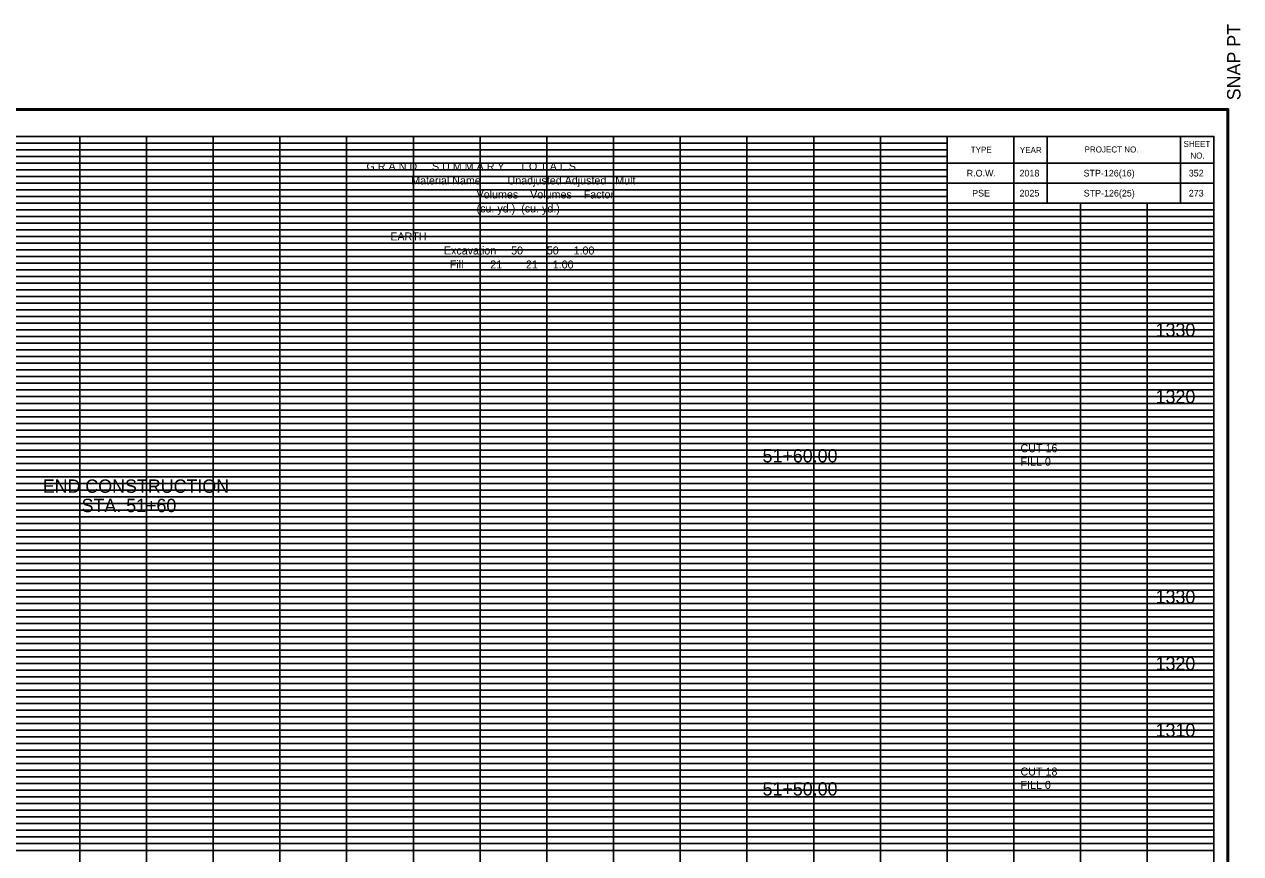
# Model space of a CAD drawing. Extents: x 980 to 1324, y 978 to 1227.
# Drawn here: x 1141.7 to 1324, y 1102.5 to 1226.8 of the extents above; entities that cross this region are included whole.
import ezdxf

# ---------------------------------------------------------------- set-up
doc = ezdxf.new("R2010")
doc.units = 0
for name, color, linetype in [('DESIGN - SCRATCH - User 1', 7, 'Continuous'), ('DESIGN - SHEET - Corner Text', 7, 'Continuous'), ('DESIGN - SHEET - Light Grid', 7, 'Continuous'), ('DESIGN - SHEET - Linework', 7, 'Continuous'), ('DESIGN - SHEET - Plot Shape', 7, 'Continuous'), ('DESIGN - TYPICAL - Finished Grade and Subgrade', 7, 'Continuous'), ('DESIGN - TYPICAL - Text', 7, 'Continuous')]:
    doc.layers.add(name, color=color, linetype=linetype)

# ---------------------------------------------------------------- blocks, each defined once
blk = doc.blocks.new('XSTSHT')
at = {"layer": 'DESIGN - SCRATCH - User 1'}
for p, q in [((28.5, 20.45), (28.5, 20.45)), ((29.24, 20.45), (29.24, 20.45)), ((30.49, 20.45), (30.49, 20.45)), ((31.74, 20.45), (31.74, 20.45)), ((28.5, 20.15), (28.5, 20.15)), ((29.24, 20.15), (29.24, 20.15)), ((30.49, 20.15), (30.49, 20.15)), ((31.74, 20.15), (31.74, 20.15))]:
    blk.add_line(p, q, dxfattribs=at)
at = {"layer": 'DESIGN - SHEET - Light Grid'}
for p, q in [((8, 20.9), (16, 20.9)), ((8, 20.8), (16, 20.8)), ((16, 20.9), (24, 20.9)), ((16, 20.8), (24, 20.8)), ((24, 20.9), (28, 20.9)), ((24, 20.8), (28, 20.8)), ((8, 20.7), (16, 20.7)), ((16, 20.7), (24, 20.7)), ((24, 20.7), (28, 20.7)), ((8, 20.6), (16, 20.6)), ((8, 20.5), (16, 20.5)), ((16, 20.6), (24, 20.6)), ((16, 20.5), (24, 20.5)), ((24, 20.6), (28, 20.6)), ((24, 20.5), (28, 20.5)), ((8, 20.4), (16, 20.4)), ((8, 20.3), (16, 20.3)), ((16, 20.4), (24, 20.4)), ((16, 20.3), (24, 20.3)), ((24, 20.4), (28, 20.4)), ((24, 20.3), (28, 20.3)), ((8, 20.2), (16, 20.2)), ((8, 20.1), (16, 20.1)), ((16, 20.2), (24, 20.2)), ((16, 20.1), (24, 20.1)), ((24, 20.2), (28, 20.2)), ((24, 20.1), (28, 20.1)), ((8, 19.9), (16, 19.9)), ((16, 19.9), (24, 19.9)), ((24, 19.9), (32, 19.9)), ((8, 19.8), (16, 19.8)), ((8, 19.7), (16, 19.7)), ((16, 19.8), (24, 19.8)), ((16, 19.7), (24, 19.7)), ((24, 19.8), (32, 19.8)), ((24, 19.7), (32, 19.7)), ((8, 19.6), (16, 19.6)), ((16, 19.6), (24, 19.6)), ((24, 19.6), (32, 19.6)), ((8, 19.5), (16, 19.5)), ((8, 19.4), (16, 19.4)), ((16, 19.5), (24, 19.5)), ((16, 19.4), (24, 19.4)), ((24, 19.5), (32, 19.5)), ((24, 19.4), (32, 19.4)), ((8, 19.3), (16, 19.3)), ((8, 19.2), (16, 19.2)), ((16, 19.3), (24, 19.3)), ((16, 19.2), (24, 19.2)), ((24, 19.3), (32, 19.3)), ((24, 19.2), (32, 19.2)), ((8, 19.1), (16, 19.1)), ((16, 19.1), (24, 19.1)), ((24, 19.1), (32, 19.1)), ((8, 18.9), (16, 18.9)), ((8, 18.8), (16, 18.8)), ((16, 18.9), (24, 18.9)), ((16, 18.8), (24, 18.8)), ((24, 18.9), (32, 18.9)), ((24, 18.8), (32, 18.8)), ((8, 18.7), (16, 18.7)), ((8, 18.6), (16, 18.6)), ((16, 18.7), (24, 18.7)), ((16, 18.6), (24, 18.6)), ((24, 18.7), (32, 18.7)), ((24, 18.6), (32, 18.6)), ((8, 18.5), (16, 18.5)), ((16, 18.5), (24, 18.5)), ((24, 18.5), (32, 18.5)), ((8, 18.4), (16, 18.4)), ((8, 18.3), (16, 18.3)), ((16, 18.4), (24, 18.4)), ((16, 18.3), (24, 18.3)), ((24, 18.4), (32, 18.4)), ((24, 18.3), (32, 18.3)), ((8, 18.2), (16, 18.2)), ((8, 18.1), (16, 18.1)), ((16, 18.2), (24, 18.2)), ((16, 18.1), (24, 18.1)), ((24, 18.2), (32, 18.2)), ((24, 18.1), (32, 18.1)), ((8, 17.9), (16, 17.9)), ((16, 17.9), (24, 17.9)), ((24, 17.9), (32, 17.9)), ((8, 17.8), (16, 17.8)), ((8, 17.7), (16, 17.7)), ((16, 17.8), (24, 17.8)), ((16, 17.7), (24, 17.7)), ((24, 17.8), (32, 17.8)), ((24, 17.7), (32, 17.7)), ((8, 17.6), (16, 17.6)), ((16, 17.6), (24, 17.6)), ((24, 17.6), (32, 17.6)), ((8, 17.5), (16, 17.5)), ((8, 17.4), (16, 17.4)), ((16, 17.5), (24, 17.5)), ((16, 17.4), (24, 17.4)), ((24, 17.5), (32, 17.5)), ((24, 17.4), (32, 17.4)), ((8, 17.3), (16, 17.3)), ((8, 17.2), (16, 17.2)), ((16, 17.3), (24, 17.3)), ((16, 17.2), (24, 17.2)), ((24, 17.3), (32, 17.3)), ((24, 17.2), (32, 17.2)), ((8, 17.1), (16, 17.1)), ((16, 17.1), (24, 17.1)), ((24, 17.1), (32, 17.1)), ((8, 16.9), (16, 16.9)), ((8, 16.8), (16, 16.8)), ((16, 16.9), (24, 16.9)), ((16, 16.8), (24, 16.8)), ((24, 16.9), (32, 16.9)), ((24, 16.8), (32, 16.8)), ((8, 16.7), (16, 16.7)), ((8, 16.6), (16, 16.6)), ((16, 16.7), (24, 16.7)), ((16, 16.6), (24, 16.6)), ((24, 16.7), (32, 16.7)), ((24, 16.6), (32, 16.6)), ((8, 16.5), (16, 16.5)), ((16, 16.5), (24, 16.5)), ((24, 16.5), (32, 16.5)), ((8, 16.4), (16, 16.4)), ((8, 16.3), (16, 16.3)), ((16, 16.4), (24, 16.4)), ((16, 16.3), (24, 16.3)), ((24, 16.4), (32, 16.4)), ((24, 16.3), (32, 16.3)), ((8, 16.2), (16, 16.2)), ((8, 16.1), (16, 16.1)), ((16, 16.2), (24, 16.2)), ((16, 16.1), (24, 16.1)), ((24, 16.2), (32, 16.2)), ((24, 16.1), (32, 16.1)), ((8, 15.9), (16, 15.9)), ((16, 15.9), (24, 15.9)), ((24, 15.9), (32, 15.9)), ((8, 15.8), (16, 15.8)), ((8, 15.7), (16, 15.7)), ((16, 15.8), (24, 15.8)), ((16, 15.7), (24, 15.7)), ((24, 15.8), (32, 15.8)), ((24, 15.7), (32, 15.7)), ((8, 15.6), (16, 15.6)), ((8, 15.5), (16, 15.5)), ((16, 15.6), (24, 15.6)), ((16, 15.5), (24, 15.5)), ((24, 15.6), (32, 15.6)), ((24, 15.5), (32, 15.5)), ((8, 15.4), (16, 15.4)), ((16, 15.4), (24, 15.4)), ((24, 15.4), (32, 15.4)), ((8, 15.3), (16, 15.3)), ((8, 15.2), (16, 15.2)), ((16, 15.3), (24, 15.3)), ((16, 15.2), (24, 15.2)), ((24, 15.3), (32, 15.3)), ((24, 15.2), (32, 15.2)), ((8, 15.1), (16, 15.1)), ((16, 15.1), (24, 15.1)), ((24, 15.1), (32, 15.1)), ((8, 14.9), (16, 14.9)), ((8, 14.8), (16, 14.8)), ((16, 14.9), (24, 14.9)), ((16, 14.8), (24, 14.8)), ((24, 14.9), (32, 14.9)), ((24, 14.8), (32, 14.8)), ((8, 14.7), (16, 14.7)), ((8, 14.6), (16, 14.6)), ((16, 14.7), (24, 14.7)), ((16, 14.6), (24, 14.6)), ((24, 14.7), (32, 14.7)), ((24, 14.6), (32, 14.6)), ((8, 14.5), (16, 14.5)), ((16, 14.5), (24, 14.5)), ((24, 14.5), (32, 14.5)), ((8, 14.4), (16, 14.4)), ((8, 14.3), (16, 14.3)), ((16, 14.4), (24, 14.4)), ((16, 14.3), (24, 14.3)), ((24, 14.4), (32, 14.4)), ((24, 14.3), (32, 14.3)), ((8, 14.2), (16, 14.2)), ((8, 14.1), (16, 14.1)), ((16, 14.2), (24, 14.2)), ((16, 14.1), (24, 14.1)), ((24, 14.2), (32, 14.2)), ((24, 14.1), (32, 14.1)), ((8, 13.9), (16, 13.9)), ((16, 13.9), (24, 13.9)), ((24, 13.9), (32, 13.9)), ((8, 13.8), (16, 13.8)), ((8, 13.7), (16, 13.7)), ((16, 13.8), (24, 13.8)), ((16, 13.7), (24, 13.7)), ((24, 13.8), (32, 13.8)), ((24, 13.7), (32, 13.7)), ((8, 13.6), (16, 13.6)), ((8, 13.5), (16, 13.5)), ((16, 13.6), (24, 13.6)), ((16, 13.5), (24, 13.5)), ((24, 13.6), (32, 13.6)), ((24, 13.5), (32, 13.5)), ((8, 13.4), (16, 13.4)), ((16, 13.4), (24, 13.4)), ((24, 13.4), (32, 13.4)), ((8, 13.3), (16, 13.3)), ((8, 13.2), (16, 13.2)), ((16, 13.3), (24, 13.3)), ((16, 13.2), (24, 13.2)), ((24, 13.3), (32, 13.3)), ((24, 13.2), (32, 13.2)), ((8, 13.1), (16, 13.1)), ((16, 13.1), (24, 13.1)), ((24, 13.1), (32, 13.1)), ((8, 12.9), (16, 12.9)), ((8, 12.8), (16, 12.8)), ((16, 12.9), (24, 12.9)), ((16, 12.8), (24, 12.8)), ((24, 12.9), (32, 12.9)), ((24, 12.8), (32, 12.8)), ((8, 12.7), (16, 12.7)), ((8, 12.6), (16, 12.6)), ((16, 12.7), (24, 12.7)), ((16, 12.6), (24, 12.6)), ((24, 12.7), (32, 12.7)), ((24, 12.6), (32, 12.6)), ((8, 12.5), (16, 12.5)), ((8, 12.4), (16, 12.4)), ((16, 12.5), (24, 12.5)), ((16, 12.4), (24, 12.4)), ((24, 12.5), (32, 12.5)), ((24, 12.4), (32, 12.4)), ((8, 12.3), (16, 12.3)), ((16, 12.3), (24, 12.3)), ((24, 12.3), (32, 12.3)), ((8, 12.2), (16, 12.2)), ((8, 12.1), (16, 12.1)), ((16, 12.2), (24, 12.2)), ((16, 12.1), (24, 12.1)), ((24, 12.2), (32, 12.2)), ((24, 12.1), (32, 12.1)), ((8, 11.9), (16, 11.9)), ((16, 11.9), (24, 11.9)), ((24, 11.9), (32, 11.9)), ((8, 11.8), (16, 11.8)), ((8, 11.7), (16, 11.7)), ((16, 11.8), (24, 11.8)), ((16, 11.7), (24, 11.7)), ((24, 11.8), (32, 11.8)), ((24, 11.7), (32, 11.7)), ((8, 11.6), (16, 11.6)), ((8, 11.5), (16, 11.5)), ((16, 11.6), (24, 11.6)), ((16, 11.5), (24, 11.5)), ((24, 11.6), (32, 11.6)), ((24, 11.5), (32, 11.5)), ((8, 11.4), (16, 11.4)), ((16, 11.4), (24, 11.4)), ((24, 11.4), (32, 11.4)), ((8, 11.3), (16, 11.3)), ((8, 11.2), (16, 11.2)), ((16, 11.3), (24, 11.3)), ((16, 11.2), (24, 11.2)), ((24, 11.3), (32, 11.3)), ((24, 11.2), (32, 11.2)), ((8, 11.1), (16, 11.1)), ((16, 11.1), (24, 11.1)), ((24, 11.1), (32, 11.1)), ((8, 10.9), (16, 10.9)), ((8, 10.8), (16, 10.8)), ((16, 10.9), (24, 10.9)), ((16, 10.8), (24, 10.8)), ((24, 10.9), (32, 10.9)), ((24, 10.8), (32, 10.8)), ((8, 10.7), (16, 10.7)), ((8, 10.6), (16, 10.6)), ((16, 10.7), (24, 10.7)), ((16, 10.6), (24, 10.6)), ((24, 10.7), (32, 10.7)), ((24, 10.6), (32, 10.6)), ((8, 10.5), (16, 10.5)), ((8, 10.4), (16, 10.4)), ((16, 10.5), (24, 10.5)), ((16, 10.4), (24, 10.4)), ((24, 10.5), (32, 10.5)), ((24, 10.4), (32, 10.4)), ((8, 10.3), (16, 10.3)), ((16, 10.3), (24, 10.3)), ((24, 10.3), (32, 10.3))]:
    blk.add_line(p, q, dxfattribs=at)
at = {"layer": 'DESIGN - SHEET - Linework'}
for p, q in [((-1.823, 21.414), (32.217, 21.414)), ((32.217, 21.414), (32.217, -0.414)), ((15, 0), (15, 21)), ((16, 0), (16, 21)), ((17, 0), (17, 21)), ((18, 0), (18, 21)), ((19, 0), (19, 21)), ((20, 0), (20, 21)), ((21, 0), (21, 21)), ((22, 0), (22, 21)), ((23, 0), (23, 21)), ((24, 0), (24, 21)), ((25, 0), (25, 21)), ((26, 0), (26, 21)), ((27, 0), (27, 21)), ((0, 20), (28, 20)), ((28, 0), (28, 20)), ((29, 0), (29, 20)), ((30, 0), (30, 20)), ((31, 0), (31, 20)), ((0, 19), (32, 19)), ((0, 18), (32, 18)), ((0, 17), (32, 17)), ((0, 16), (32, 16)), ((0, 15), (32, 15)), ((0, 14), (32, 14)), ((0, 13), (32, 13)), ((0, 12), (32, 12)), ((0, 11), (32, 11))]:
    blk.add_line(p, q, dxfattribs=at)
for points in [[(0, 21), (0, 0), (32, 0), (32, 21), (0, 21)], [(28, 21), (28, 20), (32, 20), (32, 21), (31.5, 21), (31.5, 20), (29.5, 20), (29.5, 21), (29, 21), (29, 20), (32, 20), (28, 20), (28, 20.3), (32, 20.3), (32, 20.6), (28, 20.6)]]:
    blk.add_lwpolyline(points, dxfattribs=at)
at = {"layer": 'DESIGN - SHEET - Plot Shape'}
for points in [[(-1.803, 21.394), (32.197, 21.394), (32.197, -0.394), (-1.803, -0.394)], [(-0.85, 21), (32, 21), (32, -0.25), (-0.85, -0.25)]]:
    blk.add_lwpolyline(points, close=True, dxfattribs=at)
at = {"layer": 'DESIGN - SHEET - Corner Text'}
blk.add_text('  SNAP PT', height=0.2, rotation=90, dxfattribs=at).set_placement((32.397, 21.394))
for s, p in [('TYPE', (28.354, 20.756)), ('YEAR', (29.09, 20.752)), ('PROJECT NO.', (30.06, 20.76)), ('SHEET', (31.543, 20.843)), ('NO.', (31.646, 20.669))]:
    blk.add_text(s, height=0.09, dxfattribs=at).set_placement(p)

msp = doc.modelspace()

# ---------------------------------------------------------------- block references
at = {"layer": 'DESIGN - TYPICAL - Finished Grade and Subgrade', "xscale": 10, "yscale": 10}
msp.add_blockref('XSTSHT', (1000, 1000), dxfattribs=at)

# ---------------------------------------------------------------- texts
at = {"layer": 'DESIGN - SHEET - Corner Text'}
for s, height, p in [('R.O.W.', 1, (1282.94, 1204)), ('2018', 1, (1290.85, 1204)), ('STP-126(16)', 1, (1300.45, 1204)), ('352', 1, (1316.22, 1204)), ('PSE', 1, (1283.75, 1201)), ('2025', 1, (1290.85, 1201)), ('STP-126(25)', 1, (1300.47, 1201)), ('273', 1, (1316.22, 1201)), ('1330', 2, (1311.25, 1180)), ('1320', 2, (1311.25, 1170)), ('51+60.00', 2, (1252.34, 1161.15)), ('1330', 2, (1311.25, 1140)), ('1320', 2, (1311.25, 1130)), ('1310', 2, (1311.25, 1120)), ('51+50.00', 2, (1252.34, 1111.21))]:
    msp.add_text(s, height=height, dxfattribs=at).set_placement(p)
at = {"layer": 'DESIGN - TYPICAL - Text'}
for s, height, p in [('G R A N D     S U M M A R Y     T O T A L S', 1.2, (1192.98, 1204.91)), ('               Material Name         Unadjusted Adjusted   Mult', 1.2, (1192.98, 1202.81)), ('                                     Volumes    Volumes    Factor', 1.2, (1192.98, 1200.71)), ('                                     (cu. yd.)  (cu. yd.)', 1.2, (1192.98, 1198.61)), ('        ---------------------------- ---------- ---------- ------', 1.2, (1192.98, 1196.51)), ('        EARTH', 1.2, (1192.98, 1194.41)), ('                          Excavation     50        50     1.00', 1.2, (1192.98, 1192.31)), ('                            Fill         21        21     1.00', 1.2, (1192.98, 1190.21)), ('CUT 16', 1.2, (1291, 1162.67)), ('FILL 0', 1.2, (1291, 1160.67)), ('END CONSTRUCTION', 2, (1144.45, 1156.59)), ('STA. 51+60', 2, (1150.27, 1153.69)), ('CUT 18', 1.2, (1291, 1114.21)), ('FILL 0', 1.2, (1291, 1112.21))]:
    msp.add_text(s, height=height, dxfattribs=at).set_placement(p)

doc.saveas('drawing.dxf')
